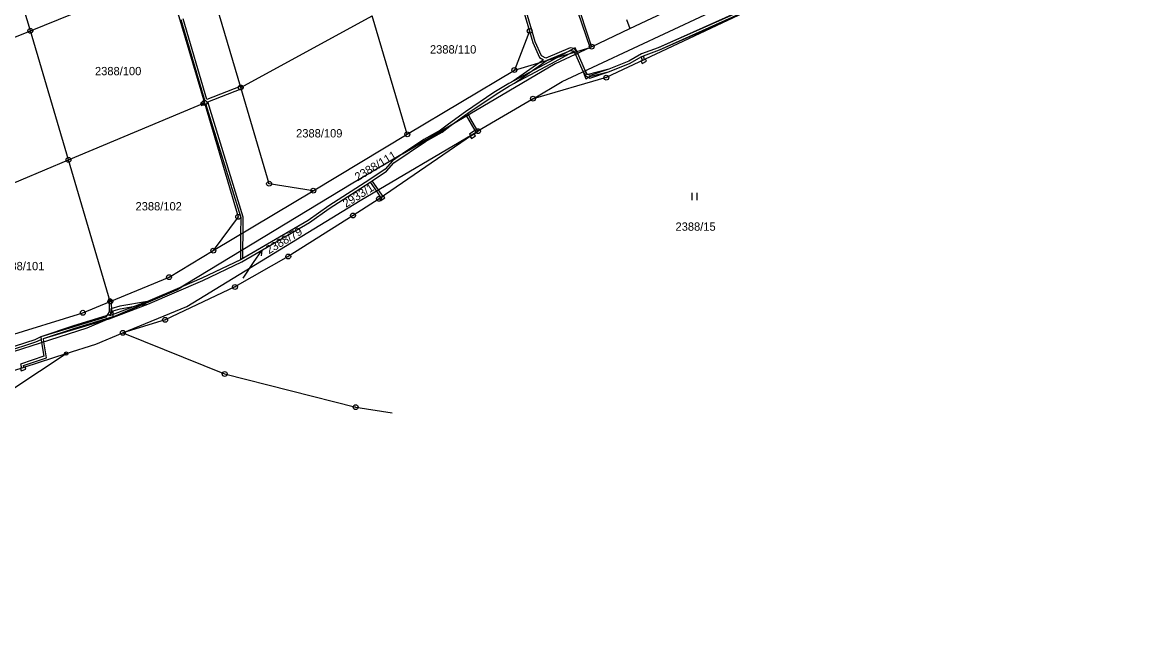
# Model space of a CAD drawing. Extents: x -758836 to -757729, y -1175316 to -1174366.
# Drawn here: x -758556.9 to -758329.3, y -1175307.5 to -1175183.4 of the extents above; entities that cross this region are included whole.
import ezdxf

# ---------------------------------------------------------------- set-up
doc = ezdxf.new("R2010")
doc.units = 0
for name, color, linetype in [('Hranice parcel', 7, 'Continuous'), ('Parcelní čísla', 7, 'Continuous'), ('Pop  PČ popisy', 7, 'Continuous'), ('Věcná břemena k části', 7, 'Continuous'), ('Značky bodu BP', 7, 'Continuous'), ('Značky kultur', 7, 'Continuous')]:
    doc.layers.add(name, color=color, linetype=linetype)

msp = doc.modelspace()

# ---------------------------------------------------------------- linework, layer by layer
at = {"layer": 'Hranice parcel'}
for p, q in [((-758461.57, -1175125.29), (-758440.3, -1175188.4)), ((-758555.19, -1175185.16), (-758562.99, -1175158.76)), ((-758512.14, -1175196.76), (-758519.81, -1175170.8)), ((-758555.19, -1175185.16), (-758527.26, -1175173.83)), ((-758527.26, -1175173.83), (-758519.56, -1175199.87)), ((-758432.48, -1175184.7), (-758415.95, -1175176.88)), ((-758512.14, -1175196.76), (-758485.2, -1175182.07)), ((-758478.03, -1175206.32), (-758485.2, -1175182.07)), ((-758440.3, -1175188.4), (-758432.48, -1175184.7)), ((-758433.19, -1175182.83), (-758432.48, -1175184.7)), ((-758583.12, -1175196.49), (-758555.19, -1175185.16)), ((-758547.39, -1175211.56), (-758555.19, -1175185.16)), ((-758456.12, -1175193.18), (-758440.6, -1175188.57)), ((-758440.3, -1175188.4), (-758440.6, -1175188.57)), ((-758478.03, -1175206.32), (-758456.12, -1175193.18)), ((-758547.39, -1175211.56), (-758519.56, -1175199.87)), ((-758452.3, -1175199.04), (-758463.57, -1175205.69)), ((-758497.27, -1175217.86), (-758478.03, -1175206.32)), ((-758575.22, -1175223.24), (-758547.39, -1175211.56)), ((-758538.83, -1175240.52), (-758547.39, -1175211.56)), ((-758517.74, -1175230.13), (-758497.27, -1175217.86))]:
    msp.add_line(p, q, dxfattribs=at)
for points in [[(-758440.6, -1175188.57), (-758462.14, -1175125.6), (-758461.57, -1175125.29)], [(-758452.3, -1175199.04), (-758446.3, -1175195.5), (-758395.2, -1175171.61), (-758348.62, -1175146.28), (-758329.33, -1175129.34)], [(-758330.11, -1175133.3), (-758340.08, -1175142.92), (-758346.47, -1175147.7), (-758393.35, -1175173.94), (-758437.3, -1175194.73), (-758452.3, -1175199.04)], [(-758458.25, -1175167.38), (-758452.99, -1175185.19), (-758456.12, -1175193.18)], [(-758440.6, -1175188.57), (-758447.78, -1175191.94), (-758489.52, -1175216.53), (-758525.18, -1175238.13), (-758543.6, -1175245.98), (-758568.36, -1175253.9), (-758575.95, -1175257.83)], [(-758497.27, -1175217.86), (-758506.32, -1175216.44), (-758512.14, -1175196.76)], [(-758519.56, -1175199.87), (-758512.66, -1175223.21), (-758517.74, -1175230.13)], [(-758536.26, -1175246.96), (-758523.13, -1175241.53), (-758487.67, -1175219.9), (-758463.57, -1175205.69)], [(-758463.57, -1175205.69), (-758483.82, -1175219.54), (-758489.14, -1175222.95), (-758502.4, -1175231.33), (-758513.31, -1175237.56), (-758527.61, -1175244.3), (-758536.26, -1175246.96)], [(-758538.83, -1175240.52), (-758526.8, -1175235.56), (-758517.74, -1175230.13)], [(-758560.34, -1175247.78), (-758544.45, -1175242.84), (-758538.83, -1175240.52)], [(-758547.85, -1175251.2), (-758541.77, -1175249.24), (-758536.26, -1175246.96)], [(-758536.26, -1175246.96), (-758515.42, -1175255.36), (-758488.6, -1175262.16), (-758481.15, -1175263.31)], [(-758572.37, -1175263.76), (-758567.46, -1175257.53), (-758547.85, -1175251.2)], [(-758564.02, -1175307.5), (-758567.06, -1175296.53), (-758567.37, -1175267.75), (-758558.79, -1175258.42), (-758547.85, -1175251.2)]]:
    msp.add_lwpolyline(points, dxfattribs=at)
at = {"layer": 'Pop  PČ popisy'}
for p, q in [((-758509.49, -1175232.56), (-758507.81, -1175230.07)), ((-758507.81, -1175230.07), (-758508.79, -1175230.62)), ((-758507.81, -1175230.07), (-758507.96, -1175231.18)), ((-758511.64, -1175235.73), (-758509.49, -1175232.56))]:
    msp.add_line(p, q, dxfattribs=at)
at = {"layer": 'Věcná břemena k části'}
for points in [[(-758458.14, -1175167.76), (-758452.99, -1175185.19), (-758452.35, -1175187.57), (-758450.96, -1175190.61), (-758450.13, -1175191.07), (-758450.93, -1175191.64), (-758456.34, -1175195.44), (-758457.23, -1175195.92), (-758460.29, -1175197.78), (-758466.12, -1175201.71), (-758469.62, -1175204.24), (-758471.22, -1175205.5), (-758474.63, -1175207.39), (-758479, -1175210.33), (-758469.33, -1175204.64), (-758466.05, -1175202.27), (-758465.62, -1175201.98), (-758459.83, -1175198.08), (-758457.09, -1175196.41), (-758456.08, -1175195.88), (-758449.43, -1175191.19), (-758444.66, -1175189.17), (-758444.11, -1175189.26), (-758443.91, -1175189.55), (-758443.61, -1175189.98), (-758443.15, -1175189.77), (-758443.41, -1175189.4), (-758443.83, -1175188.8), (-758444.72, -1175188.65), (-758449.65, -1175190.77), (-758450.58, -1175190.25), (-758451.89, -1175187.39), (-758452.51, -1175185.05), (-758457.77, -1175167.24)], [(-758524.37, -1175182.83), (-758519.46, -1175199.56), (-758519.63, -1175199.63), (-758520.38, -1175199.94), (-758520.28, -1175200.17), (-758520.18, -1175200.4), (-758519.49, -1175200.11), (-758519.31, -1175200.04), (-758512.14, -1175223.34), (-758512.16, -1175226.79), (-758512.18, -1175230.26), (-758511.68, -1175229.95), (-758511.66, -1175226.48), (-758511.64, -1175223.26), (-758518.89, -1175199.7), (-758512.07, -1175197), (-758511.59, -1175196.86), (-758511.69, -1175196.52), (-758511.73, -1175196.38), (-758512.21, -1175196.52), (-758519.04, -1175199.22), (-758523.89, -1175182.69)], [(-758410.4, -1175181.31), (-758426.7, -1175188.64), (-758430.1, -1175189.87), (-758432.68, -1175191.33), (-758436.78, -1175192.98), (-758440.62, -1175194.28), (-758441.21, -1175194.01), (-758441.6, -1175193.3), (-758443.15, -1175189.77), (-758443.61, -1175189.98), (-758442.05, -1175193.51), (-758441.57, -1175194.39), (-758440.64, -1175194.82), (-758436.62, -1175193.46), (-758432.42, -1175191.75), (-758430.14, -1175190.47), (-758429.68, -1175190.25), (-758426.42, -1175189.06), (-758410.18, -1175181.77)], [(-758410.66, -1175181.57), (-758426.7, -1175188.64), (-758430.1, -1175189.87), (-758432.68, -1175191.33), (-758436.78, -1175192.98), (-758441.29, -1175194.17), (-758441.6, -1175193.3), (-758443.15, -1175189.77), (-758443.61, -1175189.98), (-758442.05, -1175193.51), (-758441.49, -1175195.01), (-758440.72, -1175194.53), (-758436.62, -1175193.46), (-758432.42, -1175191.75), (-758430.14, -1175190.47), (-758429.94, -1175191.25), (-758429.48, -1175191.03), (-758429.68, -1175190.25), (-758426.42, -1175189.06), (-758410.46, -1175182.03)], [(-758560.31, -1175250.84), (-758554.1, -1175248.81), (-758552.99, -1175248.3), (-758552.88, -1175248.95), (-758552.4, -1175248.79), (-758552.51, -1175248.11), (-758539.08, -1175244.05), (-758525.18, -1175238.13), (-758524.18, -1175237.53), (-758531.23, -1175240.55), (-758538.96, -1175243.45), (-758538.53, -1175242.76), (-758538.58, -1175240.42), (-758538.77, -1175239.96), (-758538.97, -1175240.04), (-758538.83, -1175240.52), (-758539.08, -1175240.62), (-758539.03, -1175242.62), (-758539.73, -1175243.73), (-758553.07, -1175247.77), (-758554.28, -1175248.35), (-758560.41, -1175250.34)]]:
    msp.add_lwpolyline(points, dxfattribs=at)
for points in [[(-758443.61, -1175189.98), (-758443.15, -1175189.77), (-758443.33, -1175189.38), (-758443.66, -1175188.63), (-758447.07, -1175190.49), (-758448.92, -1175191.5), (-758457.23, -1175195.92), (-758460.29, -1175197.78), (-758466.12, -1175201.71), (-758469.62, -1175204.24), (-758471.22, -1175205.5), (-758474.63, -1175207.39), (-758479, -1175210.33), (-758469.33, -1175204.64), (-758466.05, -1175202.27), (-758465.89, -1175202.61), (-758465.45, -1175202.35), (-758465.62, -1175201.98), (-758459.83, -1175198.08), (-758457.09, -1175196.41), (-758448.68, -1175191.94), (-758444.77, -1175189.81), (-758443.9, -1175189.33), (-758443.82, -1175189.53)], [(-758429.94, -1175191.25), (-758430.18, -1175191.36), (-758429.97, -1175191.81), (-758429.07, -1175191.39), (-758429.28, -1175190.94), (-758429.48, -1175191.03)], [(-758465.08, -1175206.58), (-758465.01, -1175206.67), (-758464.37, -1175206.24), (-758463.57, -1175205.69), (-758465.2, -1175202.88), (-758465.45, -1175202.35), (-758465.89, -1175202.61), (-758465.72, -1175202.97), (-758464.23, -1175205.54), (-758465.33, -1175206.29)], [(-758485.19, -1175215.85), (-758482.27, -1175213.86), (-758480.77, -1175212.14), (-758474.33, -1175207.79), (-758470.92, -1175205.91), (-758469.33, -1175204.64), (-758479, -1175210.33), (-758481.09, -1175211.74), (-758482.59, -1175213.46), (-758485.68, -1175215.57), (-758494.08, -1175220.95), (-758498.34, -1175223.98), (-758511.69, -1175231.74), (-758511.68, -1175229.95), (-758512.18, -1175230.26), (-758512.19, -1175232.02), (-758520.09, -1175235.77), (-758524.18, -1175237.53), (-758525.18, -1175238.13), (-758539.08, -1175244.05), (-758531.11, -1175241.05), (-758519.87, -1175236.23), (-758511.87, -1175232.43), (-758498.05, -1175224.38), (-758494.02, -1175221.51), (-758485.61, -1175216.12)], [(-758482.59, -1175213.46), (-758485.68, -1175215.57), (-758494.08, -1175220.95), (-758498.34, -1175223.98), (-758512.07, -1175231.96), (-758520.09, -1175235.77), (-758524.18, -1175237.53), (-758525.18, -1175238.13), (-758532.63, -1175241.3), (-758531.11, -1175241.05), (-758519.87, -1175236.23), (-758511.87, -1175232.43), (-758498.05, -1175224.38), (-758494.02, -1175221.51), (-758485.61, -1175216.12), (-758484.37, -1175217.96), (-758483.47, -1175219.3), (-758483.05, -1175219.01), (-758483.94, -1175217.7), (-758485.19, -1175215.85), (-758482.27, -1175213.86), (-758480.77, -1175212.14), (-758474.33, -1175207.79), (-758470.92, -1175205.91), (-758469.33, -1175204.64), (-758479, -1175210.33), (-758481.09, -1175211.74)], [(-758464.91, -1175207.21), (-758464.09, -1175206.65), (-758464.37, -1175206.24), (-758465.01, -1175206.67), (-758465.19, -1175206.8)], [(-758482.87, -1175218.89), (-758483.05, -1175219.01), (-758483.47, -1175219.3), (-758483.7, -1175219.46), (-758483.42, -1175219.86), (-758482.6, -1175219.3)], [(-758552.88, -1175248.95), (-758552.4, -1175248.79), (-758552.51, -1175248.11), (-758546.1, -1175245.98), (-758538.27, -1175243.6), (-758538.23, -1175242.42), (-758536.84, -1175242.01), (-758532.63, -1175241.3), (-758525.18, -1175238.13), (-758524.18, -1175237.53), (-758531.23, -1175240.55), (-758536.9, -1175241.51), (-758538.72, -1175242.04), (-758538.76, -1175243.22), (-758546.36, -1175245.53), (-758553.07, -1175247.77)], [(-758538.97, -1175240.04), (-758539.27, -1175240.16), (-758539.08, -1175240.62), (-758538.83, -1175240.52)], [(-758556.5, -1175253.99), (-758556.59, -1175253.65), (-758551.86, -1175252.07), (-758552.4, -1175248.79), (-758552.88, -1175248.95), (-758552.42, -1175251.73), (-758557.21, -1175253.33), (-758556.97, -1175254.14), (-758557.22, -1175254.22), (-758557.06, -1175254.7), (-758556.11, -1175254.39), (-758556.27, -1175253.92)]]:
    msp.add_lwpolyline(points, close=True, dxfattribs=at)
at = {"layer": 'Značky bodu BP'}
for centre, radius in [((-758555.19, -1175185.16), 0.5), ((-758452.99, -1175185.19), 0.5), ((-758555.19, -1175185.16), 0.0303), ((-758452.99, -1175185.19), 0.0303), ((-758440.3, -1175188.4), 0.5), ((-758440.3, -1175188.4), 0.0303), ((-758456.12, -1175193.18), 0.5), ((-758456.12, -1175193.18), 0.0303), ((-758512.14, -1175196.76), 0.5), ((-758437.3, -1175194.73), 0.5), ((-758437.3, -1175194.73), 0.0303), ((-758512.14, -1175196.76), 0.0303), ((-758452.3, -1175199.04), 0.5), ((-758519.56, -1175199.87), 0.5), ((-758519.56, -1175199.87), 0.0303), ((-758452.3, -1175199.04), 0.0303), ((-758463.57, -1175205.69), 0.5), ((-758478.03, -1175206.32), 0.5), ((-758478.03, -1175206.32), 0.0303), ((-758463.57, -1175205.69), 0.0303), ((-758547.39, -1175211.56), 0.5), ((-758547.39, -1175211.56), 0.0303), ((-758506.32, -1175216.44), 0.5), ((-758506.32, -1175216.44), 0.0303), ((-758497.27, -1175217.86), 0.5), ((-758497.27, -1175217.86), 0.0303), ((-758483.82, -1175219.54), 0.5), ((-758483.82, -1175219.54), 0.0303), ((-758512.66, -1175223.21), 0.5), ((-758512.66, -1175223.21), 0.0303), ((-758489.14, -1175222.95), 0.5), ((-758489.14, -1175222.95), 0.0303), ((-758517.74, -1175230.13), 0.5), ((-758517.74, -1175230.13), 0.0303), ((-758502.4, -1175231.33), 0.5), ((-758502.4, -1175231.33), 0.0303), ((-758526.8, -1175235.56), 0.5), ((-758526.8, -1175235.56), 0.0303), ((-758513.31, -1175237.56), 0.5), ((-758513.31, -1175237.56), 0.0303), ((-758538.83, -1175240.52), 0.5), ((-758538.83, -1175240.52), 0.0303), ((-758544.45, -1175242.84), 0.5), ((-758544.45, -1175242.84), 0.0303), ((-758527.61, -1175244.3), 0.5), ((-758527.61, -1175244.3), 0.0303), ((-758536.26, -1175246.96), 0.5), ((-758536.26, -1175246.96), 0.0303), ((-758547.85, -1175251.2), 0.35), ((-758547.85, -1175251.2), 0.0212), ((-758515.42, -1175255.36), 0.5), ((-758515.42, -1175255.36), 0.0303), ((-758488.6, -1175262.16), 0.5), ((-758488.6, -1175262.16), 0.0303)]:
    msp.add_circle(centre, radius, dxfattribs=at)
at = {"layer": 'Značky kultur'}
for p, q in [((-758419.69, -1175219.81), (-758419.69, -1175218.31)), ((-758418.69, -1175219.81), (-758418.69, -1175218.31))]:
    msp.add_line(p, q, dxfattribs=at)

# ---------------------------------------------------------------- texts
at = {"layer": 'Parcelní čísla'}
for s, p in [('2388/110', (-758473.39, -1175189.8)), ('2388/100', (-758541.96, -1175194.24)), ('2388/109', (-758500.79, -1175206.97)), ('2388/102', (-758533.66, -1175221.9)), ('2388/15', (-758423.13, -1175226.06)), ('2388/101', (-758561.8, -1175234.14))]:
    msp.add_text(s, height=1.7, dxfattribs=at).set_placement(p)
for s, rotation, p in [('2388/111', 31, (-758488.17, -1175215.95)), ('2933/1', 32, (-758490.59, -1175221.38)), ('2388/79', 31, (-758506.37, -1175230.89))]:
    msp.add_text(s, height=1.7, rotation=rotation, dxfattribs=at).set_placement(p)

doc.saveas('drawing.dxf')
